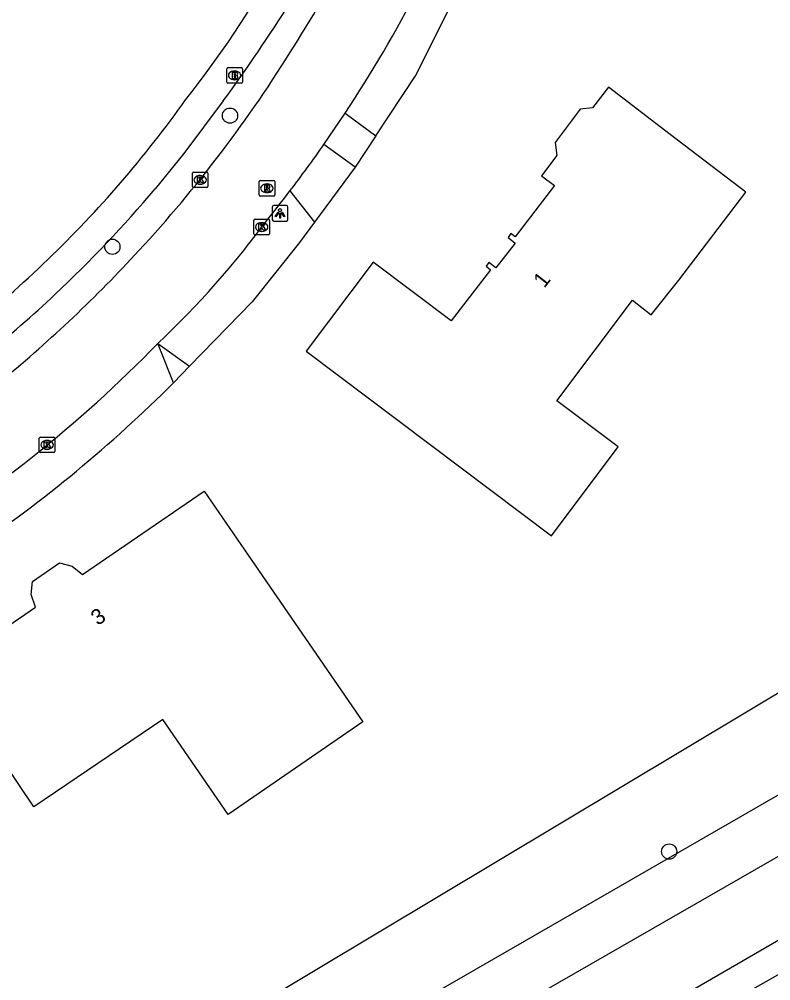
# Model space of a CAD drawing. Extents: x 162417 to 163721, y 384268 to 385416.
# Drawn here: x 163422.7 to 163470.9, y 384594.2 to 384656 of the extents above; entities that cross this region are included whole.
import ezdxf

# ---------------------------------------------------------------- set-up
doc = ezdxf.new("R2010")
doc.units = 0
for name, color, linetype in [('IMGEO_Boom', 7, 'Continuous'), ('IMGEO_Brandkraan', 7, 'Continuous'), ('IMGEO_Groenvoorziening', 7, 'Continuous'), ('IMGEO_Hek', 7, 'Continuous'), ('IMGEO_Kolk', 7, 'Continuous'), ('IMGEO_Lichtpunt', 7, 'Continuous'), ('IMGEO_Pand', 7, 'Continuous'), ('IMGEO_Pand_nummerreeks', 7, 'Continuous'), ('IMGEO_Rijbaan_lokaal_open', 7, 'Continuous'), ('IMGEO_Rioolput', 7, 'Continuous'), ('IMGEO_Voetpad_open', 7, 'Continuous')]:
    doc.layers.add(name, color=color, linetype=linetype)

msp = doc.modelspace()

# ---------------------------------------------------------------- linework, layer by layer
at = {"layer": 'IMGEO_Boom'}
for centre in [(163436.189, 384649.77), (163428.634, 384641.348), (163464.398, 384602.507)]:
    msp.add_circle(centre, 0.489, dxfattribs=at)
at = {"layer": 'IMGEO_Brandkraan'}
for p, q in [((163435.983, 384651.925), (163435.983, 384652.777)), ((163436.058, 384652.851), (163436.91, 384652.851)), ((163436.471, 384652.631), (163436.496, 384652.631)), ((163436.984, 384652.777), (163436.984, 384651.925)), ((163436.91, 384651.851), (163436.058, 384651.851)), ((163436.494, 384652.071), (163436.469, 384652.071))]:
    msp.add_line(p, q, dxfattribs=at)
for points in [[(163435.983, 384651.925), (163435.983, 384652.777)], [(163436.058, 384652.851), (163436.91, 384652.851)], [(163436.331, 384652.551), (163436.331, 384652.151), (163436.544, 384652.151)], [(163436.562, 384652.551), (163436.331, 384652.551)], [(163436.51, 384652.47), (163436.456, 384652.47), (163436.456, 384652.394)], [(163436.456, 384652.394), (163436.509, 384652.394)], [(163436.984, 384652.777), (163436.984, 384651.925)], [(163436.91, 384651.851), (163436.058, 384651.851)], [(163436.518, 384652.318), (163436.456, 384652.318), (163436.456, 384652.237)], [(163436.456, 384652.237), (163436.518, 384652.237)]]:
    msp.add_lwpolyline(points, dxfattribs=at)
for centre, radius, start, end in [((163436.06, 384652.775), 0.0765, 91.55205, 178.44795), ((163436.06, 384652.775), 0.0765, 91.55205, 178.44795), ((163436.511, 384652.432), 0.0379, 267.82845, 90.93552), ((163436.566, 384652.406), 0.145, 59.4692, 91.53667), ((163436.591, 384652.453), 0.0922, 285.51372, 58.15012), ((163436.908, 384652.775), 0.0765, 1.55205, 88.44795), ((163436.908, 384652.775), 0.0765, 1.55205, 88.44795), ((163436.06, 384651.927), 0.0765, 181.55205, 268.44795), ((163436.06, 384651.927), 0.0765, 181.55205, 268.44795), ((163436.519, 384652.277), 0.0404, 269.87594, 90.50774), ((163436.55, 384652.402), 0.251, 268.66757, 293.53466), ((163436.596, 384652.261), 0.105, 301.31148, 78.98903), ((163436.908, 384651.927), 0.0765, 271.55205, 358.44795), ((163436.908, 384651.927), 0.0765, 271.55205, 358.44795)]:
    msp.add_arc(centre, radius, start, end, dxfattribs=at)
for centre, major_axis, ratio, start_param, end_param in [((163436.47, 384652.351), (-0.387, 0.002), 0.722429, 4.712389, 7.853982), ((163436.495, 384652.351), (-0.39, 0.002), 0.717154, 1.570796, 4.712389)]:
    msp.add_ellipse(centre, major_axis=major_axis, ratio=ratio, start_param=start_param, end_param=end_param, dxfattribs=at)
at = {"layer": 'IMGEO_Groenvoorziening'}
for points in [[(163445.562, 384648.482), (163448.112, 384652.334), (163458.848, 384673.73)], [(163444.229, 384646.468), (163441.62, 384642.927)], [(163490.386, 384642.261), (163488.848, 384640.395), (163492.655, 384633.034), (163494.178, 384625.448), (163477.053, 384616.061), (163410.245, 384576.085), (163356.302, 384545.212), (163353.612, 384549.684), (163345.242, 384548.875)], [(163433.577, 384633.672), (163432.556, 384632.606)], [(163497.843, 384621.571), (163489.45, 384616.524), (163412.421, 384572.167), (163356.605, 384540.896), (163352.187, 384546.648), (163350.391, 384546.23), (163353.961, 384535.291), (163415.728, 384570.225), (163496.132, 384616.406), (163500, 384619.404), (163501.9, 384620.876)], [(163508.242, 384618.879), (163507.381, 384617.632), (163500, 384613.359), (163418.315, 384566.067), (163354.498, 384529.757)], [(163510.332, 384616.812), (163354.09, 384527.692), (163351.378, 384528.626), (163350.849, 384530.373)]]:
    msp.add_lwpolyline(points, dxfattribs=at)
at = {"layer": 'IMGEO_Hek'}
msp.add_lwpolyline([(163510.332, 384616.812), (163354.09, 384527.692), (163351.378, 384528.626), (163350.849, 384530.373)], dxfattribs=at)
at = {"layer": 'IMGEO_Kolk'}
for p, q in [((163433.772, 384645.219), (163433.772, 384646.071)), ((163433.847, 384646.145), (163434.699, 384646.145)), ((163434.26, 384645.925), (163434.285, 384645.925)), ((163434.773, 384646.071), (163434.773, 384645.219)), ((163434.699, 384645.145), (163433.847, 384645.145)), ((163434.283, 384645.365), (163434.258, 384645.365)), ((163437.726, 384642.189), (163437.726, 384643.041)), ((163437.801, 384643.115), (163438.653, 384643.115)), ((163438.214, 384642.895), (163438.239, 384642.895)), ((163438.727, 384643.041), (163438.727, 384642.189)), ((163438.653, 384642.115), (163437.801, 384642.115)), ((163438.237, 384642.335), (163438.212, 384642.335)), ((163423.941, 384628.202), (163423.941, 384629.054)), ((163424.016, 384629.128), (163424.868, 384629.128)), ((163424.942, 384629.054), (163424.942, 384628.202)), ((163424.452, 384628.348), (163424.427, 384628.348)), ((163424.429, 384628.908), (163424.454, 384628.908)), ((163424.868, 384628.128), (163424.016, 384628.128))]:
    msp.add_line(p, q, dxfattribs=at)
for points in [[(163433.772, 384645.219), (163433.772, 384646.071)], [(163433.847, 384646.145), (163434.699, 384646.145)], [(163434.093, 384645.845), (163434.216, 384645.845), (163434.216, 384645.694), (163434.346, 384645.845), (163434.51, 384645.845), (163434.364, 384645.694), (163434.517, 384645.445), (163434.365, 384645.445), (163434.28, 384645.609), (163434.216, 384645.542), (163434.216, 384645.445), (163434.093, 384645.445), (163434.093, 384645.845)], [(163434.773, 384646.071), (163434.773, 384645.219)], [(163434.699, 384645.145), (163433.847, 384645.145)], [(163437.726, 384642.189), (163437.726, 384643.041)], [(163437.801, 384643.115), (163438.653, 384643.115)], [(163438.047, 384642.815), (163438.17, 384642.815), (163438.17, 384642.664), (163438.3, 384642.815), (163438.464, 384642.815), (163438.318, 384642.664), (163438.471, 384642.415), (163438.319, 384642.415), (163438.234, 384642.579), (163438.17, 384642.512), (163438.17, 384642.415), (163438.047, 384642.415), (163438.047, 384642.815)], [(163438.727, 384643.041), (163438.727, 384642.189)], [(163438.653, 384642.115), (163437.801, 384642.115)], [(163423.941, 384628.202), (163423.941, 384629.054)], [(163424.016, 384629.128), (163424.868, 384629.128)], [(163424.942, 384629.054), (163424.942, 384628.202)], [(163424.262, 384628.828), (163424.385, 384628.828), (163424.385, 384628.677), (163424.515, 384628.828), (163424.679, 384628.828), (163424.533, 384628.677), (163424.686, 384628.428), (163424.534, 384628.428), (163424.449, 384628.592), (163424.385, 384628.525), (163424.385, 384628.428), (163424.262, 384628.428), (163424.262, 384628.828)], [(163424.868, 384628.128), (163424.016, 384628.128)]]:
    msp.add_lwpolyline(points, dxfattribs=at)
for centre, start, end in [((163433.849, 384646.069), 91.55205, 178.44795), ((163433.849, 384646.069), 91.55205, 178.44795), ((163434.697, 384646.069), 1.55205, 88.44795), ((163434.697, 384646.069), 1.55205, 88.44795), ((163433.849, 384645.221), 181.55205, 268.44795), ((163433.849, 384645.221), 181.55205, 268.44795), ((163434.697, 384645.221), 271.55205, 358.44795), ((163434.697, 384645.221), 271.55205, 358.44795), ((163437.803, 384643.039), 91.55205, 178.44795), ((163437.803, 384643.039), 91.55205, 178.44795), ((163438.651, 384643.039), 1.55205, 88.44795), ((163438.651, 384643.039), 1.55205, 88.44795), ((163437.803, 384642.191), 181.55205, 268.44795), ((163437.803, 384642.191), 181.55205, 268.44795), ((163438.651, 384642.191), 271.55205, 358.44795), ((163438.651, 384642.191), 271.55205, 358.44795), ((163424.018, 384629.052), 91.55205, 178.44795), ((163424.018, 384629.052), 91.55205, 178.44795), ((163424.866, 384629.052), 1.55205, 88.44795), ((163424.866, 384629.052), 1.55205, 88.44795), ((163424.018, 384628.204), 181.55205, 268.44795), ((163424.018, 384628.204), 181.55205, 268.44795), ((163424.866, 384628.204), 271.55205, 358.44795), ((163424.866, 384628.204), 271.55205, 358.44795)]:
    msp.add_arc(centre, 0.0765, start, end, dxfattribs=at)
for centre, major_axis, ratio, start_param, end_param in [((163434.259, 384645.645), (-0.387, 0.002), 0.722429, 4.712389, 7.853982), ((163434.284, 384645.645), (-0.39, 0.002), 0.717154, 1.570796, 4.712389), ((163438.213, 384642.615), (-0.387, 0.002), 0.722429, 4.712389, 7.853982), ((163438.238, 384642.615), (-0.39, 0.002), 0.717154, 1.570796, 4.712389), ((163424.428, 384628.628), (-0.387, 0.002), 0.722429, 4.712389, 7.853982), ((163424.453, 384628.628), (-0.39, 0.002), 0.717154, 1.570796, 4.712389)]:
    msp.add_ellipse(centre, major_axis=major_axis, ratio=ratio, start_param=start_param, end_param=end_param, dxfattribs=at)
at = {"layer": 'IMGEO_Lichtpunt'}
for p, q in [((163438.906, 384643.901), (163438.906, 384643.094)), ((163438.906, 384643.901), (163438.906, 384643.094)), ((163439.808, 384643.996), (163439, 384643.996)), ((163439.808, 384643.996), (163439, 384643.996)), ((163439.902, 384643.094), (163439.902, 384643.901)), ((163439.902, 384643.094), (163439.902, 384643.901)), ((163439, 384643), (163439.808, 384643)), ((163439, 384643), (163439.808, 384643))]:
    msp.add_line(p, q, dxfattribs=at)
for points in [[(163439.28, 384643.565), (163439.319, 384643.537), (163439.131, 384643.275), (163439.093, 384643.302), (163439.28, 384643.565)], [(163439.382, 384643.517), (163439.429, 384643.517), (163439.429, 384643.195), (163439.382, 384643.195), (163439.382, 384643.517)], [(163439.492, 384643.537), (163439.53, 384643.564), (163439.717, 384643.302), (163439.678, 384643.274), (163439.492, 384643.537)]]:
    msp.add_lwpolyline(points, dxfattribs=at)
msp.add_circle((163439.405, 384643.699), 0.0994, dxfattribs=at)
for centre, start, end in [((163439, 384643.901), 90, 180), ((163439, 384643.901), 90, 180), ((163439.808, 384643.901), 0, 90), ((163439.808, 384643.901), 0, 90), ((163439, 384643.094), 180, 270), ((163439, 384643.094), 180, 270), ((163439.808, 384643.094), 270, 0), ((163439.808, 384643.094), 270, 360)]:
    msp.add_arc(centre, 0.0946, start, end, dxfattribs=at)
at = {"layer": 'IMGEO_Pand'}
for points in [[(163456.834, 384622.787), (163461.128, 384628.492), (163457.183, 384631.465), (163462.05, 384637.926), (163463.234, 384636.978), (163465.023, 384639.213), (163469.329, 384644.852), (163464.466, 384648.566), (163460.492, 384651.6), (163459.478, 384650.272), (163458.687, 384650.185), (163457.07, 384648.042), (163457.188, 384647.216), (163456.192, 384645.905), (163457.021, 384645.287), (163454.511, 384641.994), (163454.23, 384642.204), (163454.052, 384641.949), (163454.503, 384641.582), (163453.271, 384640.002), (163452.824, 384640.343), (163452.64, 384640.096), (163452.913, 384639.878), (163450.384, 384636.587), (163445.376, 384640.357), (163441.077, 384634.645), (163445.072, 384631.638), (163456.834, 384622.787)], [(163423.426, 384619.015), (163423.504, 384619.857), (163425.24, 384621.047), (163426.06, 384620.847), (163426.722, 384620.31), (163434.524, 384625.652), (163437.361, 384621.535), (163444.73, 384610.844), (163436.077, 384604.88), (163431.875, 384610.985), (163423.588, 384605.386), (163421.696, 384608.187), (163420.775, 384607.881), (163419.813, 384608.066), (163419.044, 384608.641), (163418.702, 384609.538), (163418.883, 384610.501), (163419.499, 384611.264), (163417.6, 384614.035), (163423.689, 384618.208), (163423.426, 384619.015)]]:
    msp.add_lwpolyline(points, dxfattribs=at)
at = {"layer": 'IMGEO_Rijbaan_lokaal_open'}
msp.add_lwpolyline([(163442.225, 384647.922), (163443.594, 384649.939)], dxfattribs=at)
for centre, radius, start, end in [((163372.322, 384697.23), 80.439, 327.69017, 333.08477), ((163370.348, 384698.203), 87.718, 326.61785, 332.66515), ((163367.687, 384699.024), 85.321, 317.24489, 328.33568), ((163368.427, 384699.601), 90.094, 322.64513, 324.99712), ((163371.918, 384696.918), 85.691, 321.10831, 322.65514), ((163390.205, 384678.824), 60.154, 313.43502, 323.58755), ((163366.109, 384700.117), 87.222, 309.51339, 317.42123), ((163370.506, 384694.597), 85.221, 301.14686, 315.76166)]:
    msp.add_arc(centre, radius, start, end, dxfattribs=at)
at = {"layer": 'IMGEO_Rioolput'}
for p, q in [((163438.132, 384645.608), (163438.984, 384645.608)), ((163438.057, 384644.682), (163438.057, 384645.534)), ((163438.545, 384645.388), (163438.57, 384645.388)), ((163439.058, 384645.534), (163439.058, 384644.682)), ((163438.984, 384644.608), (163438.132, 384644.608)), ((163438.568, 384644.828), (163438.543, 384644.828))]:
    msp.add_line(p, q, dxfattribs=at)
for points in [[(163438.132, 384645.608), (163438.984, 384645.608)], [(163438.057, 384644.682), (163438.057, 384645.534)], [(163438.646, 384645.306), (163438.394, 384645.308), (163438.394, 384644.908)], [(163438.394, 384644.908), (163438.518, 384644.908), (163438.518, 384645.07), (163438.529, 384645.07)], [(163438.572, 384645.227), (163438.518, 384645.227), (163438.518, 384645.146)], [(163438.518, 384645.146), (163438.57, 384645.146)], [(163438.576, 384645.041), (163438.647, 384644.908), (163438.787, 384644.908), (163438.722, 384645.034)], [(163439.058, 384645.534), (163439.058, 384644.682)], [(163438.984, 384644.608), (163438.132, 384644.608)]]:
    msp.add_lwpolyline(points, dxfattribs=at)
for centre, radius, start, end in [((163438.134, 384645.532), 0.0765, 91.55205, 178.44795), ((163438.134, 384645.532), 0.0765, 91.55205, 178.44795), ((163438.982, 384645.532), 0.0765, 1.55205, 88.44795), ((163438.982, 384645.532), 0.0765, 1.55205, 88.44795), ((163438.528, 384645.017), 0.0533, 26.02933, 88.69889), ((163438.554, 384645.335), 0.19, 274.7715, 282.96867), ((163438.578, 384645.131), 0.0964, 77.00612, 93.18647), ((163438.592, 384645.188), 0.0378, 276.66336, 79.67722), ((163438.645, 384645.196), 0.109, 350.36119, 89.41601), ((163438.643, 384645.196), 0.112, 277.58423, 350.98172), ((163438.627, 384644.981), 0.108, 29.51342, 73.79051), ((163438.134, 384644.684), 0.0765, 181.55205, 268.44795), ((163438.134, 384644.684), 0.0765, 181.55205, 268.44795), ((163438.982, 384644.684), 0.0765, 271.55205, 358.44795), ((163438.982, 384644.684), 0.0765, 271.55205, 358.44795)]:
    msp.add_arc(centre, radius, start, end, dxfattribs=at)
for centre, major_axis, ratio, start_param, end_param in [((163438.544, 384645.108), (-0.387, 0.002), 0.722429, 4.712389, 7.853982), ((163438.569, 384645.108), (-0.39, 0.002), 0.717154, 1.570796, 4.712389)]:
    msp.add_ellipse(centre, major_axis=major_axis, ratio=ratio, start_param=start_param, end_param=end_param, dxfattribs=at)
at = {"layer": 'IMGEO_Voetpad_open'}
for points in [[(163435.757, 384650.725), (163433.233, 384647.339), (163431.375, 384645.06)], [(163443.594, 384649.939), (163445.562, 384648.482)], [(163445.562, 384648.482), (163444.229, 384646.468)], [(163444.229, 384646.468), (163442.225, 384647.922)], [(163440.042, 384644.937), (163441.62, 384642.927)], [(163441.62, 384642.927), (163440.661, 384641.624), (163437.621, 384637.821), (163433.577, 384633.672)], [(163432.556, 384632.606), (163431.562, 384635.143)], [(163431.562, 384635.143), (163433.577, 384633.672)]]:
    msp.add_lwpolyline(points, dxfattribs=at)
for centre, radius, start, end in [((163383.007, 384690.738), 64.258, 321.562, 330.99773), ((163349.96, 384713.846), 106.515, 323.65813, 327.78495), ((163374.28, 384692.806), 72.479, 313.8396, 324.57181), ((163369, 384697.794), 81.679, 313.23065, 319.78787), ((163373.98, 384692.802), 72.684, 308.65684, 314.01186), ((163375.608, 384690.545), 71.872, 308.65738, 313.34994), ((163368.694, 384696.602), 90.409, 304.2543, 314.94032)]:
    msp.add_arc(centre, radius, start, end, dxfattribs=at)

# ---------------------------------------------------------------- texts
at = {"layer": 'IMGEO_Pand_nummerreeks'}
for s, rotation, p in [('1', 52.05479, (163456.374, 384638.648)), ('3', 34.46655, (163427.691, 384616.984))]:
    msp.add_text(s, height=1, rotation=rotation, dxfattribs=at).set_placement(p)

doc.saveas('drawing.dxf')
